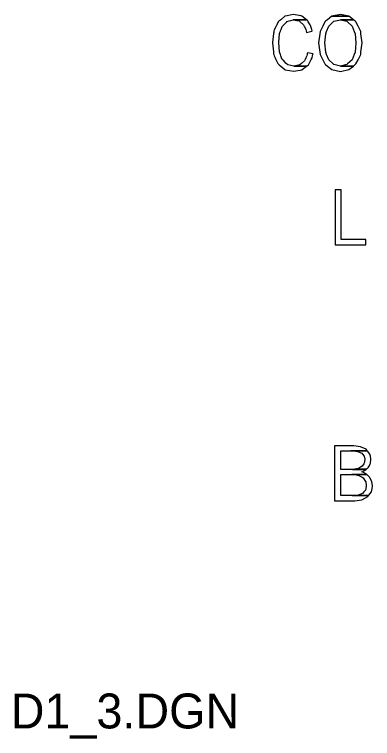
# Model space of a CAD drawing. Extents: x 0.013 to 0.187, y -0.092 to 0.261.
# Drawn here: x 0.01279 to 0.02828, y 0.00393 to 0.0353 of the extents above; entities that cross this region are included whole.
import ezdxf

# ---------------------------------------------------------------- set-up
doc = ezdxf.new("R2010")
doc.units = 0
doc.layers.add('1', color=7, linetype='Continuous')

msp = doc.modelspace()

# ---------------------------------------------------------------- linework, layer by layer
at = {"layer": '1'}
for points in [[(0.024503, 0.032909), (0.02487, 0.032838), (0.025235, 0.032909), (0.025239, 0.032912), (0.02543, 0.033065), (0.024881, 0.033065), (0.024614, 0.033124), (0.024611, 0.033125), (0.024609, 0.033126), (0.024609, 0.033126), (0.024551, 0.033183), (0.024551, 0.033183), (0.024444, 0.033289), (0.024375, 0.033357), (0.024349, 0.033428), (0.024318, 0.03351), (0.024297, 0.033567), (0.024288, 0.033592), (0.024254, 0.033685), (0.024223, 0.034069), (0.024221, 0.034092), (0.024258, 0.034473), (0.024277, 0.034526), (0.024298, 0.034585), (0.0243, 0.03459), (0.024323, 0.034656), (0.024367, 0.034775), (0.024388, 0.034798), (0.024438, 0.034849), (0.024567, 0.034985), (0.024573, 0.034991), (0.024671, 0.035021), (0.024742, 0.035042), (0.024741, 0.035042), (0.02485, 0.035075), (0.025423, 0.035075), (0.025223, 0.035221), (0.025222, 0.035221), (0.025193, 0.035242), (0.024851, 0.035301), (0.024851, 0.035301), (0.024584, 0.035242), (0.024487, 0.035221), (0.024313, 0.035075), (0.024274, 0.035042), (0.024248, 0.035021), (0.024213, 0.034991), (0.024205, 0.034985), (0.02414, 0.034849), (0.024115, 0.034798), (0.024104, 0.034775), (0.024046, 0.034656), (0.024014, 0.03459), (0.024011, 0.034585), (0.024005, 0.034526), (0.023998, 0.034473), (0.023955, 0.034092), (0.023953, 0.034069), (0.023993, 0.033685), (0.024003, 0.033592), (0.024005, 0.033567), (0.024031, 0.03351), (0.024068, 0.033428), (0.024099, 0.033357), (0.02413, 0.033289), (0.024177, 0.033183), (0.024242, 0.033126), (0.024244, 0.033125), (0.024245, 0.033124), (0.024312, 0.033065), (0.024487, 0.032912)], [(0.026519, 0.032914), (0.02689, 0.032837), (0.027261, 0.032914), (0.02745, 0.033067), (0.026889, 0.033067), (0.026608, 0.033131), (0.026579, 0.033159), (0.026386, 0.033343), (0.026296, 0.033571), (0.026256, 0.033672), (0.026214, 0.034069), (0.026256, 0.034466), (0.026296, 0.034567), (0.026386, 0.034795), (0.026579, 0.034979), (0.026608, 0.035007), (0.026889, 0.035072), (0.02745, 0.035072), (0.027261, 0.035224), (0.026519, 0.035224), (0.02633, 0.035072), (0.02625, 0.035007), (0.026216, 0.034979), (0.026125, 0.034795), (0.026012, 0.034567), (0.025999, 0.034466), (0.025947, 0.034069), (0.025999, 0.033672), (0.026012, 0.033571), (0.026125, 0.033343), (0.026216, 0.033159), (0.02625, 0.033131), (0.02633, 0.033067)], [(0.02689, 0.035301), (0.026519, 0.035224), (0.027261, 0.035224)], [(0.02541, 0.034585), (0.025425, 0.034526), (0.025652, 0.034585), (0.025673, 0.03459), (0.025653, 0.034656), (0.025653, 0.034656), (0.025618, 0.034775), (0.025611, 0.034798), (0.025581, 0.034849), (0.025502, 0.034985), (0.025502, 0.034985), (0.025498, 0.034991), (0.025481, 0.035021), (0.025468, 0.035042), (0.025423, 0.035075), (0.02485, 0.035075), (0.025007, 0.035042), (0.025109, 0.035021), (0.025142, 0.034991), (0.025149, 0.034985), (0.025297, 0.034849), (0.025322, 0.034798), (0.025333, 0.034775), (0.025391, 0.034656), (0.025408, 0.03459)], [(0.027171, 0.033131), (0.026889, 0.033067), (0.02745, 0.033067), (0.02753, 0.033131), (0.02753, 0.033131), (0.027564, 0.033159), (0.027655, 0.033343), (0.027768, 0.033571), (0.027781, 0.033672), (0.027833, 0.034069), (0.027781, 0.034466), (0.027768, 0.034567), (0.027655, 0.034795), (0.027564, 0.034979), (0.02753, 0.035007), (0.02753, 0.035007), (0.02745, 0.035072), (0.026889, 0.035072), (0.027171, 0.035007), (0.0272, 0.034979), (0.027393, 0.034795), (0.027482, 0.034567), (0.027522, 0.034466), (0.027564, 0.034069), (0.027522, 0.033672), (0.027482, 0.033571), (0.027393, 0.033343), (0.0272, 0.033159)], [(0.025139, 0.033124), (0.024881, 0.033065), (0.02543, 0.033065), (0.025503, 0.033124), (0.025505, 0.033125), (0.025504, 0.033125), (0.025507, 0.033126), (0.025536, 0.033183), (0.025591, 0.033289), (0.025626, 0.033357), (0.025663, 0.033428), (0.025687, 0.03351), (0.025703, 0.033567), (0.02571, 0.033592), (0.025471, 0.033645), (0.025458, 0.033592), (0.025453, 0.033567), (0.025439, 0.03351), (0.025399, 0.033428), (0.025365, 0.033357), (0.025332, 0.033289), (0.025209, 0.033183), (0.025142, 0.033126), (0.02514, 0.033125)], [(0.026657, 0.025546), (0.026657, 0.025316), (0.027993, 0.025316), (0.027993, 0.025546), (0.026927, 0.025546), (0.026927, 0.027703), (0.026657, 0.027703)], [(0.026642, 0.014231), (0.026642, 0.014228), (0.027367, 0.014228), (0.027521, 0.014231), (0.027816, 0.014274), (0.028076, 0.014414), (0.028109, 0.014458), (0.026902, 0.014458), (0.026902, 0.014461), (0.026902, 0.014479), (0.026902, 0.014552), (0.026902, 0.014618), (0.026902, 0.014696), (0.026902, 0.014854), (0.026902, 0.014875), (0.026902, 0.015068), (0.026902, 0.015074), (0.026902, 0.01523), (0.026902, 0.015255), (0.026902, 0.015331), (0.026902, 0.015367), (0.026902, 0.01537), (0.02803, 0.01537), (0.028016, 0.015384), (0.027885, 0.015458), (0.027821, 0.015486), (0.027886, 0.015512), (0.027991, 0.015574), (0.02801, 0.015592), (0.026902, 0.015592), (0.026902, 0.015598), (0.026902, 0.015632), (0.026902, 0.015682), (0.026902, 0.015726), (0.026902, 0.015828), (0.026902, 0.015862), (0.026902, 0.016014), (0.026902, 0.01603), (0.026902, 0.016163), (0.026902, 0.016256), (0.026902, 0.016289), (0.026902, 0.016373), (0.026902, 0.016399), (0.026902, 0.0164), (0.028055, 0.0164), (0.028005, 0.016463), (0.02776, 0.016574), (0.027467, 0.016612), (0.027288, 0.016615), (0.026642, 0.016615), (0.026642, 0.016612), (0.026642, 0.016574), (0.026642, 0.016463), (0.026642, 0.0164), (0.026642, 0.016399), (0.026642, 0.016373), (0.026642, 0.016289), (0.026642, 0.016256), (0.026642, 0.016163), (0.026642, 0.01603), (0.026642, 0.016014), (0.026642, 0.015862), (0.026642, 0.015828), (0.026642, 0.015726), (0.026642, 0.015682), (0.026642, 0.015632), (0.026642, 0.015598), (0.026642, 0.015592), (0.026642, 0.015574), (0.026642, 0.015512), (0.026642, 0.015486), (0.026642, 0.015458), (0.026642, 0.015384), (0.026642, 0.01537), (0.026642, 0.015367), (0.026642, 0.015331), (0.026642, 0.015255), (0.026642, 0.01523), (0.026642, 0.015074), (0.026642, 0.015068), (0.026642, 0.014875), (0.026642, 0.014854), (0.026642, 0.014696), (0.026642, 0.014618), (0.026642, 0.014552), (0.026642, 0.014479), (0.026642, 0.014461), (0.026642, 0.014458), (0.026642, 0.014414), (0.026642, 0.014274)], [(0.027337, 0.0164), (0.027438, 0.016399), (0.028055, 0.016399), (0.028055, 0.0164)], [(0.027673, 0.015632), (0.027506, 0.015598), (0.028016, 0.015598), (0.028052, 0.015632), (0.028105, 0.015682), (0.028129, 0.015726), (0.028185, 0.015828), (0.02819, 0.015862), (0.028189, 0.015862), (0.02821, 0.016014), (0.028213, 0.01603), (0.028186, 0.016163), (0.028168, 0.016256), (0.028142, 0.016289), (0.028076, 0.016373), (0.028055, 0.016399), (0.027438, 0.016399), (0.027635, 0.016373), (0.027822, 0.016289), (0.027846, 0.016256), (0.027916, 0.016163), (0.027942, 0.01603), (0.027945, 0.016014), (0.027923, 0.015862), (0.027902, 0.015828), (0.027837, 0.015726), (0.027761, 0.015682)], [(0.027505, 0.015598), (0.02741, 0.015592), (0.02801, 0.015592), (0.028016, 0.015598)], [(0.027658, 0.014479), (0.027484, 0.014461), (0.028111, 0.014461), (0.028125, 0.014479), (0.02818, 0.014552), (0.02823, 0.014618), (0.028246, 0.014696), (0.028279, 0.014854), (0.028276, 0.014875), (0.02825, 0.015068), (0.028249, 0.015074), (0.028165, 0.01523), (0.028152, 0.015255), (0.028071, 0.015331), (0.028033, 0.015367), (0.02803, 0.01537), (0.027392, 0.01537), (0.027511, 0.015367), (0.027693, 0.015331), (0.027832, 0.015255), (0.027876, 0.01523), (0.027983, 0.015074), (0.027987, 0.015068), (0.02801, 0.014875), (0.028006, 0.014854), (0.027972, 0.014696), (0.027903, 0.014618), (0.027845, 0.014552)], [(0.027484, 0.014461), (0.027393, 0.014458), (0.028109, 0.014458), (0.028111, 0.014461)]]:
    msp.add_lwpolyline(points, close=True, dxfattribs=at)

# ---------------------------------------------------------------- texts
msp.add_text('D1_3.DGN', height=0.001512, dxfattribs=at).set_placement((0.012625, 0.004369))

doc.saveas('drawing.dxf')
